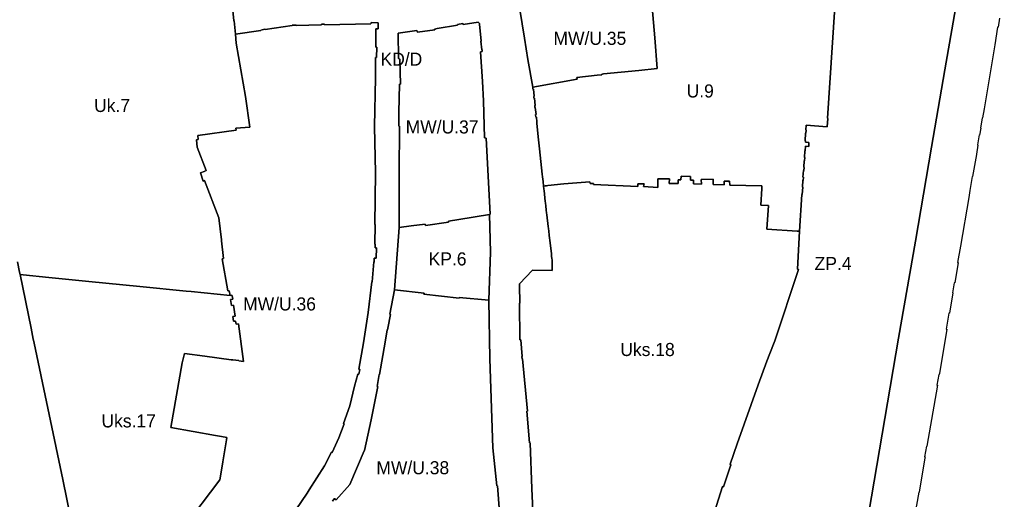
# Model space of a CAD drawing. Extents: x 7423367 to 7424726, y 5546744 to 5548391.
# Drawn here: x 7423781.7 to 7424156.6, y 5547186.6 to 5547370 of the extents above; entities that cross this region are included whole.
import ezdxf

# ---------------------------------------------------------------- set-up
doc = ezdxf.new("R2010")
doc.units = 0
doc.layers.add('linie_rozgraniczajace', color=7, linetype='Continuous')
doc.layers.add('oznaczenia_przeznaczen', color=7, linetype='Continuous')

msp = doc.modelspace()

# ---------------------------------------------------------------- linework, layer by layer
at = {"layer": 'linie_rozgraniczajace'}
for points in [[(7424142.07, 5547387.31), (7424135.74, 5547350.81), (7424130.64, 5547321.23), (7424124.48, 5547285.32), (7424118.04, 5547248.25), (7424112.79, 5547217.43), (7424107.64, 5547187.5), (7424099.83, 5547142.6)], [(7424099.83, 5547142.6), (7424107.64, 5547187.5), (7424112.79, 5547217.43), (7424118.04, 5547248.25), (7424124.48, 5547285.32), (7424130.64, 5547321.23), (7424135.74, 5547350.81), (7424142.07, 5547387.31)], [(7423862.4, 5547382.77), (7423863.66, 5547369.51), (7423863.82, 5547369.52), (7423864.39, 5547364.38), (7423864.55, 5547360.96), (7423868.18, 5547340.63), (7423869.78, 5547328.91), (7423864.52, 5547328.49), (7423864.65, 5547327.69), (7423849.92, 5547325.61), (7423850.11, 5547324.13), (7423849.76, 5547324.09), (7423849.46, 5547324.06), (7423849.66, 5547321.26), (7423853.08, 5547312.25), (7423852.29, 5547311.92), (7423851, 5547311.38), (7423851.91, 5547308.25), (7423852.46, 5547308.41), (7423858, 5547294.14), (7423858.93, 5547285.81), (7423858.97, 5547285.41), (7423859.72, 5547278.62), (7423859.23, 5547278.51), (7423861.41, 5547266.27), (7423861.97, 5547266.26), (7423862.29, 5547264.55), (7423852.32, 5547265.56), (7423847.39, 5547266), (7423845.46, 5547266.18), (7423827.71, 5547267.92), (7423808.22, 5547269.83), (7423792.94, 5547271.39), (7423783.14, 5547272.4), (7423781.99, 5547272.51), (7423781.77, 5547273.48), (7423780.9, 5547277.38)], [(7423887.37, 5547182.59), (7423891.7, 5547188.9), (7423892.56, 5547190.24), (7423898.38, 5547199.43), (7423901.03, 5547204.61), (7423901.38, 5547204.46), (7423903.82, 5547210.05), (7423905.92, 5547215.45), (7423905.61, 5547215.57), (7423908.11, 5547222.37), (7423909.83, 5547229.87), (7423911.13, 5547234.41), (7423911.48, 5547234.42), (7423911.88, 5547236.21), (7423911.56, 5547236.35), (7423913.33, 5547246.43), (7423915.06, 5547258.04), (7423916.46, 5547269.74), (7423916.66, 5547269.71), (7423917.28, 5547277.31), (7423917.37, 5547277.3), (7423917.45, 5547278.75), (7423918.1, 5547278.71), (7423918.32, 5547282.7), (7423917.75, 5547282.71), (7423917.74, 5547284.14), (7423917.63, 5547284.15), (7423917.82, 5547291.66), (7423917.69, 5547291.67), (7423917.86, 5547311.45), (7423917.53, 5547329.12), (7423917.96, 5547347.77), (7423917.96, 5547355.51), (7423918.34, 5547355.51), (7423918.36, 5547359.48), (7423918.05, 5547359.48), (7423918.08, 5547366.42), (7423918.92, 5547366.44), (7423918.93, 5547368.8), (7423916.18, 5547368.92), (7423916.12, 5547368.31), (7423898.36, 5547367.99), (7423898.35, 5547368.25), (7423897.26, 5547368.21), (7423897.27, 5547367.97), (7423887.61, 5547367.74), (7423887.61, 5547367.87), (7423885.96, 5547367.8), (7423885.96, 5547367.67), (7423875.63, 5547366.16), (7423875.61, 5547366.26), (7423873.97, 5547366), (7423874, 5547365.81), (7423864.39, 5547364.38), (7423863.82, 5547369.52), (7423863.66, 5547369.51), (7423862.4, 5547382.77)], [(7424093.59, 5547374.75), (7424090.88, 5547332.24), (7424090.96, 5547332.23), (7424090.7, 5547329.01), (7424082.7, 5547329.57), (7424082.48, 5547327.8), (7424082.67, 5547327.75), (7424082.59, 5547326.58), (7424082.4, 5547326.61), (7424082.27, 5547323.63), (7424082.42, 5547323.59), (7424082.37, 5547323.13), (7424083.72, 5547323.02), (7424083.64, 5547321.47), (7424082.37, 5547321.53), (7424082.27, 5547319.85), (7424082.11, 5547319.87), (7424081.98, 5547317.29), (7424082.14, 5547317.28), (7424082.03, 5547316.03), (7424081.87, 5547316.04), (7424081.7, 5547313.51), (7424081.86, 5547313.49), (7424081.78, 5547312.24), (7424081.62, 5547312.25), (7424081.42, 5547309.73), (7424081.58, 5547309.72), (7424081.52, 5547308.52), (7424081.36, 5547308.54), (7424081.23, 5547305.98), (7424081.39, 5547305.97), (7424081.16, 5547303.11), (7424081, 5547303.12), (7424080.15, 5547289.11), (7424079.2, 5547289.13), (7424067.56, 5547289.85), (7424068.23, 5547298.94), (7424065.3, 5547299.07), (7424065.66, 5547305.4), (7424065.72, 5547306.38), (7424053.43, 5547306.73), (7424053.38, 5547308.22), (7424051.33, 5547308.21), (7424051.33, 5547306.87), (7424047.04, 5547306.95), (7424047.07, 5547308.95), (7424042.52, 5547308.81), (7424042.59, 5547307.07), (7424039.49, 5547307.21), (7424039.49, 5547308.56), (7424038.38, 5547308.54), (7424038.35, 5547310.01), (7424034.79, 5547310.08), (7424034.72, 5547308.68), (7424033.71, 5547308.72), (7424033.67, 5547307.29), (7424030.27, 5547307.32), (7424030.32, 5547309.06), (7424025.97, 5547309.08), (7424025.91, 5547305.8), (7424020.47, 5547306.14), (7424020.62, 5547307.22), (7424018.27, 5547307.25), (7424018.23, 5547306.17), (7424001.33, 5547306.99), (7424001.32, 5547307.36), (7424000.01, 5547307.33), (7423999.9, 5547307.98), (7423989.95, 5547307.19), (7423983.88, 5547306.54), (7423983.33, 5547306.49), (7423982.75, 5547306.43), (7423982.17, 5547306.36), (7423982, 5547308.06), (7423981.81, 5547309.92), (7423981.71, 5547310.84), (7423980.68, 5547320.54), (7423980.32, 5547323.98), (7423979.66, 5547330.24), (7423979.59, 5547330.9), (7423979.48, 5547332.73), (7423979.27, 5547332.71), (7423979.15, 5547333.65), (7423979.31, 5547333.68), (7423979.04, 5547336.4), (7423978.86, 5547336.39), (7423978.79, 5547337.15), (7423978.95, 5547337.17), (7423978.68, 5547339.89), (7423978.5, 5547339.88), (7423978.43, 5547340.63), (7423978.59, 5547340.65), (7423978.3, 5547343.36), (7423978.14, 5547343.36), (7423978.05, 5547344.11), (7423995.06, 5547347.15), (7423994.96, 5547347.87), (7424002.72, 5547348.68), (7424004.48, 5547348.87), (7424004.44, 5547349.15), (7424005.17, 5547349.22), (7424018.6, 5547350.49), (7424025.62, 5547351.34), (7424024.7, 5547363.07), (7424023.54, 5547377.76)], [(7423973.13, 5547373.87), (7423974.91, 5547362.9), (7423976.14, 5547354.78), (7423978.05, 5547344.11), (7423978.14, 5547343.36), (7423978.3, 5547343.36), (7423978.59, 5547340.65), (7423978.43, 5547340.63), (7423978.5, 5547339.88), (7423978.68, 5547339.89), (7423978.95, 5547337.17), (7423978.79, 5547337.15), (7423978.86, 5547336.39), (7423979.04, 5547336.4), (7423979.31, 5547333.68), (7423979.15, 5547333.65), (7423979.27, 5547332.71), (7423979.48, 5547332.73), (7423979.59, 5547330.9), (7423979.66, 5547330.24), (7423980.32, 5547323.98), (7423980.68, 5547320.54), (7423981.71, 5547310.84), (7423981.81, 5547309.92), (7423982, 5547308.06), (7423982.17, 5547306.36), (7423982.3, 5547305.25), (7423982.39, 5547304.53), (7423982.52, 5547303.42), (7423982.72, 5547301.67), (7423982.85, 5547300.57), (7423982.93, 5547299.83), (7423983.06, 5547298.72), (7423983.24, 5547297.18), (7423983.37, 5547296.07), (7423983.46, 5547295.32), (7423983.59, 5547294.21), (7423983.84, 5547292.04), (7423983.97, 5547290.93), (7423984.06, 5547290.13), (7423984.19, 5547289.06), (7423984.36, 5547287.53), (7423984.5, 5547286.41), (7423984.59, 5547285.65), (7423984.72, 5547284.54), (7423985.07, 5547281.52), (7423985.2, 5547280.41), (7423985.29, 5547279.67), (7423985.42, 5547278.55), (7423985.43, 5547278.26), (7423985.47, 5547274.09), (7423977.93, 5547274.19), (7423973.02, 5547268.99), (7423972.99, 5547268.34), (7423973.12, 5547261.51), (7423972.95, 5547261.51), (7423973.12, 5547247.55), (7423973.44, 5547247.57), (7423974.06, 5547241.15), (7423973.9, 5547241.14), (7423973.98, 5547240.29), (7423974.14, 5547240.29), (7423976, 5547220.33), (7423975.73, 5547220.29), (7423976.85, 5547208.22), (7423977.1, 5547208.18), (7423977.1, 5547208.11), (7423977.66, 5547190.74), (7423978.47, 5547173.56)], [(7424045.15, 5547174.18), (7424050.63, 5547191.5), (7424051.05, 5547191.36), (7424053.62, 5547198.95), (7424053.86, 5547199.69), (7424053.53, 5547199.98), (7424056.28, 5547207.79), (7424064.23, 5547230.4), (7424067.67, 5547239.42), (7424070.15, 5547245.93), (7424070.64, 5547247.23), (7424079.67, 5547274.49), (7424079.29, 5547274.52), (7424080.15, 5547289.11), (7424081, 5547303.12), (7424081.16, 5547303.11), (7424081.39, 5547305.97), (7424081.23, 5547305.98), (7424081.36, 5547308.54), (7424081.52, 5547308.52), (7424081.58, 5547309.72), (7424081.42, 5547309.73), (7424081.62, 5547312.25), (7424081.78, 5547312.24), (7424081.86, 5547313.49), (7424081.7, 5547313.51), (7424081.87, 5547316.04), (7424082.03, 5547316.03), (7424082.14, 5547317.28), (7424081.98, 5547317.29), (7424082.11, 5547319.87), (7424082.27, 5547319.85), (7424082.37, 5547321.53), (7424083.64, 5547321.47), (7424083.72, 5547323.02), (7424082.37, 5547323.13), (7424082.42, 5547323.59), (7424082.27, 5547323.63), (7424082.4, 5547326.61), (7424082.59, 5547326.58), (7424082.67, 5547327.75), (7424082.48, 5547327.8), (7424082.7, 5547329.57), (7424090.7, 5547329.01), (7424090.96, 5547332.23), (7424090.88, 5547332.24), (7424093.59, 5547374.75)], [(7424156.58, 5547370.57), (7424156.11, 5547367.04), (7424155.86, 5547367.08), (7424154.77, 5547360.35), (7424150.74, 5547335.86), (7424150.1, 5547332.37), (7424149.93, 5547332.4), (7424149.34, 5547328.53), (7424149.48, 5547328.51), (7424149.02, 5547325.85), (7424148.86, 5547325.88), (7424148.21, 5547322.04), (7424148.36, 5547322.01), (7424147.82, 5547318.59), (7424147.85, 5547318.45), (7424146.32, 5547309.99), (7424146.16, 5547310.02), (7424145.3, 5547304.67), (7424144.87, 5547301.94), (7424141.67, 5547283.34), (7424140.6, 5547277.09), (7424140.76, 5547277.06), (7424139.47, 5547269.3), (7424139.31, 5547269.33), (7424138.67, 5547265.49), (7424138.82, 5547265.46), (7424137.5, 5547257.72), (7424137.29, 5547257.76), (7424136.27, 5547251.61), (7424136.46, 5547251.58), (7424133.66, 5547234.72), (7424133.58, 5547234.27), (7424133.39, 5547234.3), (7424132.7, 5547230.21), (7424132.84, 5547230.18), (7424128.79, 5547206.93), (7424128.67, 5547206.95), (7424127.97, 5547202.8), (7424128.16, 5547202.76), (7424128.09, 5547202.41), (7424128, 5547202.43), (7424125.85, 5547189.3), (7424125.73, 5547189.33), (7424122.09, 5547168.69)], [(7423844.47, 5547175.64), (7423858.41, 5547194.06), (7423859.26, 5547199.29), (7423859.52, 5547200.89), (7423860.9, 5547209.32), (7423861.03, 5547210.21), (7423858.94, 5547210.59), (7423856.74, 5547210.98), (7423839.54, 5547214.08), (7423843.95, 5547238.71), (7423844.04, 5547239.22), (7423844.83, 5547242.34), (7423852.58, 5547241.31), (7423862.66, 5547239.94), (7423863.32, 5547239.9), (7423865.58, 5547239.68), (7423865.56, 5547239.46), (7423867.34, 5547239.3), (7423865.55, 5547253.71), (7423864.55, 5547253.57), (7423864.39, 5547254.75), (7423863.61, 5547254.64), (7423863.34, 5547256.53), (7423864.24, 5547256.66), (7423863.6, 5547260.82), (7423862.76, 5547260.69), (7423862.4, 5547262.96), (7423863.26, 5547263.11), (7423863.14, 5547263.82), (7423862.98, 5547264.69), (7423862.29, 5547264.55), (7423861.97, 5547266.26), (7423861.41, 5547266.27), (7423859.23, 5547278.51), (7423859.72, 5547278.62), (7423858.97, 5547285.41), (7423858.93, 5547285.81), (7423858, 5547294.14), (7423852.46, 5547308.41), (7423851.91, 5547308.25), (7423851, 5547311.38), (7423852.29, 5547311.92), (7423853.08, 5547312.25), (7423849.66, 5547321.26), (7423849.46, 5547324.06), (7423849.76, 5547324.09), (7423850.11, 5547324.13), (7423849.92, 5547325.61), (7423864.65, 5547327.69), (7423864.52, 5547328.49), (7423869.78, 5547328.91), (7423868.18, 5547340.63), (7423864.55, 5547360.96), (7423864.39, 5547364.38), (7423874, 5547365.81), (7423873.97, 5547366), (7423875.61, 5547366.26), (7423875.63, 5547366.16), (7423885.96, 5547367.67), (7423885.96, 5547367.8), (7423887.61, 5547367.87), (7423887.61, 5547367.74), (7423897.27, 5547367.97), (7423897.26, 5547368.21), (7423898.35, 5547368.25), (7423898.36, 5547367.99), (7423916.12, 5547368.31), (7423916.18, 5547368.92), (7423918.93, 5547368.8), (7423918.92, 5547366.44), (7423918.08, 5547366.42), (7423918.05, 5547359.48), (7423918.36, 5547359.48), (7423918.34, 5547355.51), (7423917.96, 5547355.51), (7423917.96, 5547347.77), (7423917.53, 5547329.12), (7423917.86, 5547311.45), (7423917.69, 5547291.67), (7423917.82, 5547291.66), (7423917.63, 5547284.15), (7423917.74, 5547284.14), (7423917.75, 5547282.71), (7423918.32, 5547282.7), (7423918.1, 5547278.71), (7423917.45, 5547278.75), (7423917.37, 5547277.3), (7423917.28, 5547277.31), (7423916.66, 5547269.71), (7423916.46, 5547269.74), (7423915.06, 5547258.04), (7423913.33, 5547246.43), (7423911.56, 5547236.35), (7423911.88, 5547236.21), (7423911.48, 5547234.42), (7423911.13, 5547234.41), (7423909.83, 5547229.87), (7423908.11, 5547222.37), (7423905.61, 5547215.57), (7423905.92, 5547215.45), (7423903.82, 5547210.05), (7423901.38, 5547204.46), (7423901.03, 5547204.61), (7423898.38, 5547199.43), (7423892.56, 5547190.24), (7423891.7, 5547188.9), (7423887.37, 5547182.59)], [(7423965.29, 5547181.66), (7423964.53, 5547191.7), (7423964.36, 5547191.72), (7423962.81, 5547206.21), (7423961.66, 5547240.26), (7423961.29, 5547262.74), (7423961.86, 5547281.1), (7423961.47, 5547295.44), (7423961.77, 5547295.6), (7423960.21, 5547324.61), (7423959.65, 5547324.84), (7423959.16, 5547338.97), (7423958.77, 5547346.35), (7423958.06, 5547357.69), (7423958.7, 5547357.73), (7423958.73, 5547358.38), (7423958.58, 5547358.39), (7423958.19, 5547361.76), (7423958.34, 5547361.78), (7423957.68, 5547368.19), (7423957.65, 5547368.43), (7423957.2, 5547368.98), (7423951.38, 5547368.07), (7423951.3, 5547368.51), (7423949.23, 5547368.16), (7423949.29, 5547367.81), (7423941.52, 5547366.53), (7423940.5, 5547366.35), (7423940.57, 5547366.07), (7423933.91, 5547365.17), (7423933.73, 5547365.75), (7423926.55, 5547364.81), (7423926.69, 5547355.05), (7423927.26, 5547354.88), (7423927.47, 5547345.29), (7423927.14, 5547345.28), (7423926.87, 5547334.47), (7423926.82, 5547329.21), (7423927.12, 5547329.21), (7423927.13, 5547323.11), (7423926.94, 5547317.2), (7423926.9, 5547290.48), (7423925.17, 5547266.69), (7423923.4, 5547257.31), (7423923.63, 5547257.27), (7423922.63, 5547251.98), (7423922.51, 5547251.33), (7423922.37, 5547251.36), (7423921.55, 5547246.67), (7423921.65, 5547246.65), (7423919.48, 5547234.3), (7423919.35, 5547234.32), (7423918.56, 5547229.74), (7423918.73, 5547229.7), (7423916.25, 5547216.95), (7423913.64, 5547205.29), (7423913.59, 5547205.06), (7423908.05, 5547192.2), (7423902.85, 5547186.33), (7423902.4, 5547186.79), (7423902.14, 5547186.78), (7423901.41, 5547185.86)], [(7423978.47, 5547173.56), (7423977.66, 5547190.74), (7423977.1, 5547208.11), (7423977.1, 5547208.18), (7423976.85, 5547208.22), (7423975.73, 5547220.29), (7423976, 5547220.33), (7423974.14, 5547240.29), (7423973.98, 5547240.29), (7423973.9, 5547241.14), (7423974.06, 5547241.15), (7423973.44, 5547247.57), (7423973.12, 5547247.55), (7423972.95, 5547261.51), (7423973.12, 5547261.51), (7423972.99, 5547268.34), (7423973.02, 5547268.99), (7423977.93, 5547274.19), (7423985.47, 5547274.09), (7423985.43, 5547278.26), (7423985.42, 5547278.55), (7423985.29, 5547279.67), (7423985.2, 5547280.41), (7423985.07, 5547281.52), (7423984.72, 5547284.54), (7423984.59, 5547285.65), (7423984.5, 5547286.41), (7423984.36, 5547287.53), (7423984.19, 5547289.06), (7423984.06, 5547290.13), (7423983.97, 5547290.93), (7423983.84, 5547292.04), (7423983.59, 5547294.21), (7423983.46, 5547295.32), (7423983.37, 5547296.07), (7423983.24, 5547297.18), (7423983.06, 5547298.72), (7423982.93, 5547299.83), (7423982.85, 5547300.57), (7423982.72, 5547301.67), (7423982.52, 5547303.42), (7423982.39, 5547304.53), (7423982.3, 5547305.25), (7423982.17, 5547306.36), (7423982.75, 5547306.43), (7423983.33, 5547306.49), (7423983.88, 5547306.54), (7423989.95, 5547307.19), (7423999.9, 5547307.98), (7424000.01, 5547307.33), (7424001.32, 5547307.36), (7424001.33, 5547306.99), (7424018.23, 5547306.17), (7424018.27, 5547307.25), (7424020.62, 5547307.22), (7424020.47, 5547306.14), (7424025.91, 5547305.8), (7424025.97, 5547309.08), (7424030.32, 5547309.06), (7424030.27, 5547307.32), (7424033.67, 5547307.29), (7424033.71, 5547308.72), (7424034.72, 5547308.68), (7424034.79, 5547310.08), (7424038.35, 5547310.01), (7424038.38, 5547308.54), (7424039.49, 5547308.56), (7424039.49, 5547307.21), (7424042.59, 5547307.07), (7424042.52, 5547308.81), (7424047.07, 5547308.95), (7424047.04, 5547306.95), (7424051.33, 5547306.87), (7424051.33, 5547308.21), (7424053.38, 5547308.22), (7424053.43, 5547306.73), (7424065.72, 5547306.38), (7424065.66, 5547305.4), (7424065.3, 5547299.07), (7424068.23, 5547298.94), (7424067.56, 5547289.85), (7424079.2, 5547289.13), (7424080.15, 5547289.11), (7424079.29, 5547274.52), (7424079.67, 5547274.49), (7424070.64, 5547247.23), (7424070.15, 5547245.93), (7424067.67, 5547239.42), (7424064.23, 5547230.4), (7424056.28, 5547207.79), (7424053.53, 5547199.98), (7424053.86, 5547199.69), (7424053.62, 5547198.95), (7424051.05, 5547191.36), (7424050.63, 5547191.5), (7424045.15, 5547174.18)], [(7423780.9, 5547277.38), (7423781.77, 5547273.48), (7423781.99, 5547272.51), (7423786.19, 5547252.01), (7423786.97, 5547247.83), (7423787.16, 5547246.93), (7423787.29, 5547246.31), (7423798.24, 5547194.18), (7423801.4, 5547179.17), (7423807.26, 5547151.49), (7423802.44, 5547148.02), (7423795.99, 5547146.38), (7423788.2, 5547143.63), (7423771.74, 5547137.77)], [(7423801.4, 5547179.17), (7423798.24, 5547194.18), (7423787.29, 5547246.31), (7423787.16, 5547246.93), (7423786.97, 5547247.83), (7423786.19, 5547252.01), (7423781.99, 5547272.51), (7423783.14, 5547272.4), (7423792.94, 5547271.39), (7423808.22, 5547269.83), (7423827.71, 5547267.92), (7423845.46, 5547266.18), (7423847.39, 5547266), (7423852.32, 5547265.56), (7423862.29, 5547264.55), (7423862.98, 5547264.69), (7423863.14, 5547263.82), (7423863.26, 5547263.11), (7423862.4, 5547262.96), (7423862.76, 5547260.69), (7423863.6, 5547260.82), (7423864.24, 5547256.66), (7423863.34, 5547256.53), (7423863.61, 5547254.64), (7423864.39, 5547254.75), (7423864.55, 5547253.57), (7423865.55, 5547253.71), (7423867.34, 5547239.3), (7423865.56, 5547239.46), (7423865.58, 5547239.68), (7423863.32, 5547239.9), (7423862.66, 5547239.94), (7423852.58, 5547241.31), (7423844.83, 5547242.34), (7423844.04, 5547239.22), (7423843.95, 5547238.71), (7423839.54, 5547214.08), (7423856.74, 5547210.98), (7423858.94, 5547210.59), (7423861.03, 5547210.21), (7423860.9, 5547209.32), (7423859.52, 5547200.89), (7423859.26, 5547199.29), (7423858.41, 5547194.06), (7423844.47, 5547175.64)], [(7423901.41, 5547185.86), (7423902.14, 5547186.78), (7423902.4, 5547186.79), (7423902.85, 5547186.33), (7423908.05, 5547192.2), (7423913.59, 5547205.06), (7423913.64, 5547205.29), (7423916.25, 5547216.95), (7423918.73, 5547229.7), (7423918.56, 5547229.74), (7423919.35, 5547234.32), (7423919.48, 5547234.3), (7423921.65, 5547246.65), (7423921.55, 5547246.67), (7423922.37, 5547251.36), (7423922.51, 5547251.33), (7423922.63, 5547251.98), (7423923.63, 5547257.27), (7423923.4, 5547257.31), (7423925.17, 5547266.69), (7423936.46, 5547265.37), (7423936.42, 5547265.04), (7423949.89, 5547263.43), (7423949.93, 5547263.77), (7423961.29, 5547262.74), (7423961.66, 5547240.26), (7423962.81, 5547206.21), (7423964.36, 5547191.72), (7423964.53, 5547191.7), (7423965.29, 5547181.66)]]:
    msp.add_lwpolyline(points, dxfattribs=at)
for points in [[(7423973.13, 5547373.87), (7423974.57, 5547374.13), (7423974.87, 5547373.46), (7424023.01, 5547381.2), (7424023.27, 5547381.24), (7424023.54, 5547377.76), (7424024.7, 5547363.07), (7424025.62, 5547351.34), (7424018.6, 5547350.49), (7424005.17, 5547349.22), (7424004.44, 5547349.15), (7424004.48, 5547348.87), (7424002.72, 5547348.68), (7423994.96, 5547347.87), (7423995.06, 5547347.15), (7423978.05, 5547344.11), (7423976.14, 5547354.78), (7423974.91, 5547362.9)], [(7423926.9, 5547290.48), (7423926.94, 5547317.2), (7423927.13, 5547323.11), (7423927.12, 5547329.21), (7423926.82, 5547329.21), (7423926.87, 5547334.47), (7423927.14, 5547345.28), (7423927.47, 5547345.29), (7423927.26, 5547354.88), (7423926.69, 5547355.05), (7423926.55, 5547364.81), (7423933.73, 5547365.75), (7423933.91, 5547365.17), (7423940.57, 5547366.07), (7423940.5, 5547366.35), (7423941.52, 5547366.53), (7423949.29, 5547367.81), (7423949.23, 5547368.16), (7423951.3, 5547368.51), (7423951.38, 5547368.07), (7423957.2, 5547368.98), (7423957.65, 5547368.43), (7423957.68, 5547368.19), (7423958.34, 5547361.78), (7423958.19, 5547361.76), (7423958.58, 5547358.39), (7423958.73, 5547358.38), (7423958.7, 5547357.73), (7423958.06, 5547357.69), (7423958.77, 5547346.35), (7423959.16, 5547338.97), (7423959.65, 5547324.84), (7423960.21, 5547324.61), (7423961.77, 5547295.6), (7423961.47, 5547295.44), (7423949.75, 5547293.54), (7423945.81, 5547292.98), (7423945.88, 5547292.58), (7423936.98, 5547291.21), (7423936.9, 5547291.8), (7423931.57, 5547291.1)], [(7423925.17, 5547266.69), (7423926.9, 5547290.48), (7423931.57, 5547291.1), (7423936.9, 5547291.8), (7423936.98, 5547291.21), (7423945.88, 5547292.58), (7423945.81, 5547292.98), (7423949.75, 5547293.54), (7423961.47, 5547295.44), (7423961.86, 5547281.1), (7423961.29, 5547262.74), (7423949.93, 5547263.77), (7423949.89, 5547263.43), (7423936.42, 5547265.04), (7423936.46, 5547265.37)]]:
    msp.add_lwpolyline(points, close=True, dxfattribs=at)

# ---------------------------------------------------------------- texts
at = {"layer": 'oznaczenia_przeznaczen'}
for s, p in [('MW/U.35', (7423985.98, 5547360.32)), ('KD/D', (7423919.82, 5547352.37)), ('U.9', (7424036.92, 5547340.2)), ('Uk.7', (7423810.26, 5547334.65)), ('MW/U.37', (7423929.44, 5547326.44)), ('KP.6', (7423938.22, 5547275.99)), ('ZP.4', (7424085.88, 5547274.23)), ('MW/U.36', (7423867.25, 5547258.77)), ('Uks.18', (7424011.56, 5547241.35)), ('Uks.17', (7423813.07, 5547214.06)), ('MW/U.38', (7423918.22, 5547196.16))]:
    msp.add_text(s, height=5, dxfattribs=at).set_placement(p)

doc.saveas('drawing.dxf')
